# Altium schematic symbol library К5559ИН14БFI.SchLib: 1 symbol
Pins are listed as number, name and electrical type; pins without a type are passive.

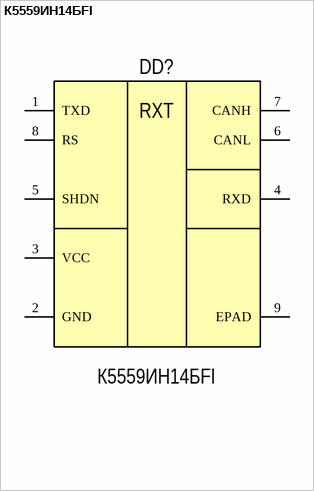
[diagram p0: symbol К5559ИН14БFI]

## К5559ИН14БFI
designator DD?  Part Number: К5559ИН14БFI
FullName: Микросхема К5559ИН14БFI ТСКЯ.431000.003ТУ, ТСКЯ.431323.049СП; Поставщик: Миландр
footprint К5559ИН14БFI (DFN8 5x6x0,75 (1,27))
pins: 1 TXD, 2 GND, 3 VCC, 4 RXD, 5 SHDN, 6 CANL, 7 CANH, 8 RS, 9 EPAD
